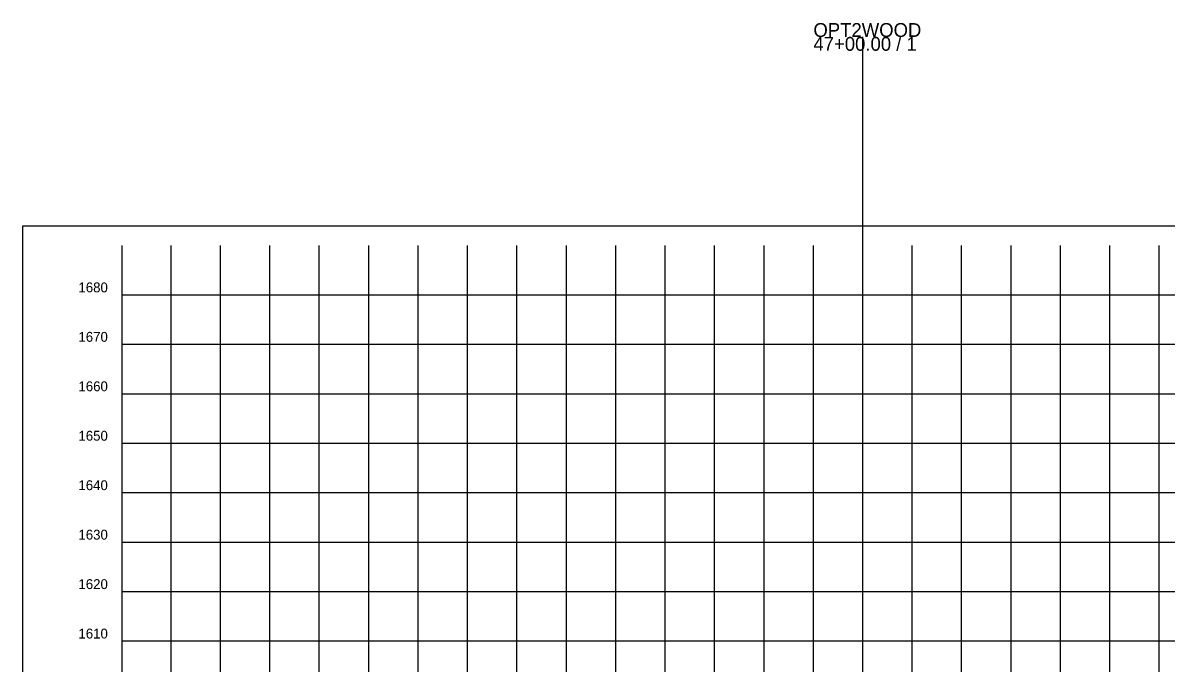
# Model space of a CAD drawing. Extents: x -26 to 2998798, y -429 to 819149.
# Drawn here: x 130 to 361.4, y 2568.5 to 2698 of the extents above; entities that cross this region are included whole.
import ezdxf

# ---------------------------------------------------------------- set-up
doc = ezdxf.new("R2010")
doc.units = 0
for name, color, linetype in [('DESIGN - SHEET - Corner Text', 7, 'Continuous'), ('DESIGN - SHEET - Light Grid', 7, 'Continuous'), ('DESIGN - SHEET - Linework', 7, 'Continuous'), ('DESIGN - SHEET - Plot Shape', 7, 'Continuous')]:
    doc.layers.add(name, color=color, linetype=linetype)

msp = doc.modelspace()

# ---------------------------------------------------------------- linework, layer by layer
at = {"layer": 'DESIGN - SHEET - Light Grid'}
msp.add_line((300, 2500), (300, 2695.15), dxfattribs=at)
at = {"layer": 'DESIGN - SHEET - Linework'}
for p, q in [((160, 2443), (160, 2653)), ((170, 2443), (170, 2653)), ((180, 2443), (180, 2653)), ((190, 2443), (190, 2653)), ((200, 2443), (200, 2653)), ((210, 2443), (210, 2653)), ((220, 2443), (220, 2653)), ((230, 2443), (230, 2653)), ((240, 2443), (240, 2653)), ((250, 2443), (250, 2653)), ((260, 2443), (260, 2653)), ((270, 2443), (270, 2653)), ((280, 2443), (280, 2653)), ((290, 2443), (290, 2653)), ((300, 2443), (300, 2653)), ((310, 2443), (310, 2653)), ((320, 2443), (320, 2653)), ((330, 2443), (330, 2653)), ((340, 2443), (340, 2653)), ((350, 2443), (350, 2653)), ((360, 2443), (360, 2653)), ((150, 2643), (450, 2643)), ((150, 2633), (450, 2633)), ((150, 2623), (450, 2623)), ((150, 2613), (450, 2613)), ((150, 2603), (450, 2603)), ((150, 2593), (450, 2593)), ((150, 2583), (450, 2583)), ((150, 2573), (450, 2573))]:
    msp.add_line(p, q, dxfattribs=at)
msp.add_lwpolyline([(150, 2653), (150, 2443), (450, 2443), (450, 2653)], dxfattribs=at)
at = {"layer": 'DESIGN - SHEET - Plot Shape'}
msp.add_lwpolyline([(130, 2656.94), (470, 2656.94), (470, 2439.06), (130, 2439.06)], close=True, dxfattribs=at)

# ---------------------------------------------------------------- texts
at = {"layer": 'DESIGN - SHEET - Corner Text'}
for s, p in [('1680', (141.25, 2643.5)), ('1670', (141.25, 2633.5)), ('1660', (141.25, 2623.5)), ('1650', (141.25, 2613.5)), ('1640', (141.25, 2603.5)), ('1630', (141.25, 2593.5)), ('1620', (141.25, 2583.5)), ('1610', (141.25, 2573.5))]:
    msp.add_text(s, height=2, dxfattribs=at).set_placement(p)
at = {"layer": 'DESIGN - SHEET - Light Grid'}
for s, p in [('OPT2WOOD', (290, 2695.15)), ('47+00.00 / 1', (290, 2692.35))]:
    msp.add_text(s, height=2.8, dxfattribs=at).set_placement(p)

doc.saveas('drawing.dxf')
